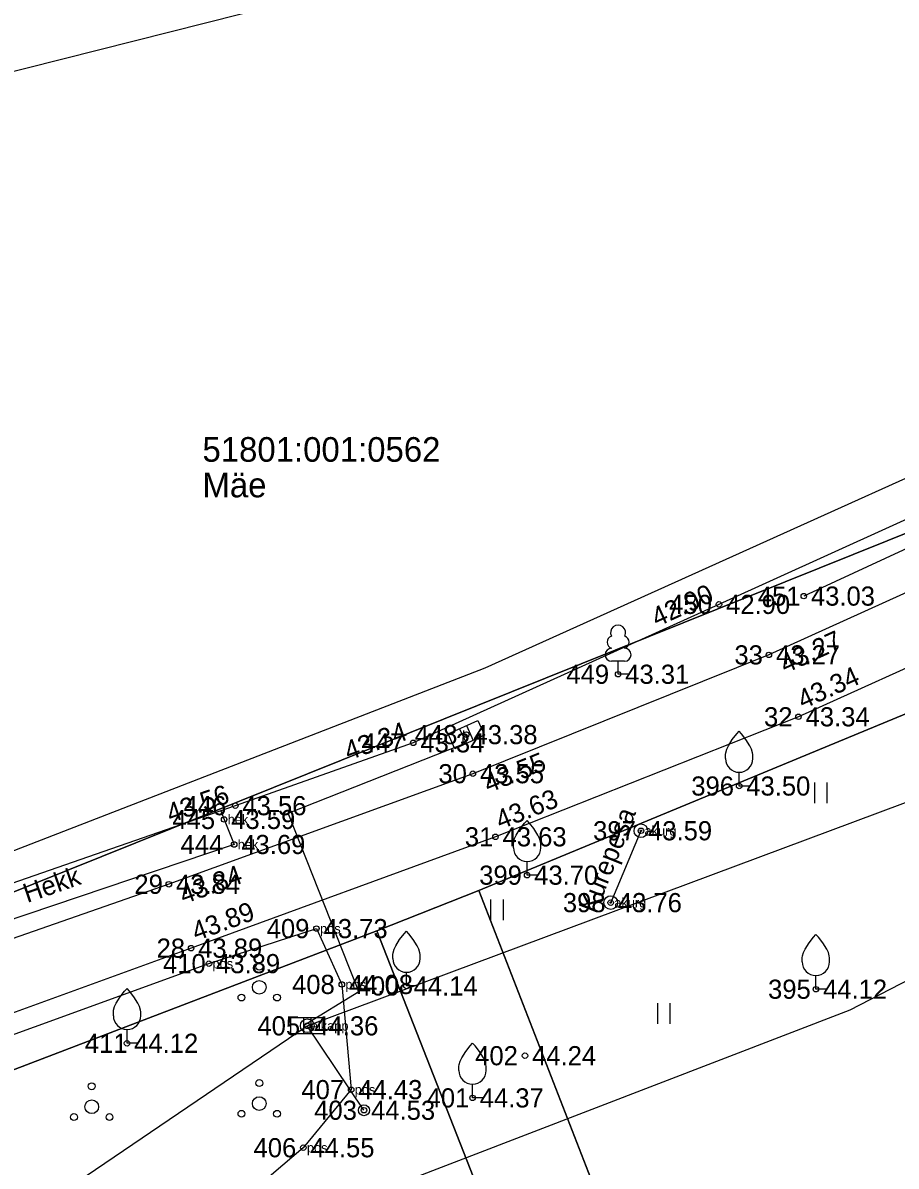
# Model space of a CAD drawing. Extents: x 505800 to 507326, y 6540058 to 6542128.
# Drawn here: x 506036.42 to 506068.35, y 6540204 to 6540245.78 of the extents above; entities that cross this region are included whole.
import ezdxf

# ---------------------------------------------------------------- set-up
doc = ezdxf.new("R2010")
doc.units = 0
for name, color, linetype in [('AED', 7, 'Continuous'), ('ELRAJATISMP', 7, 'Continuous'), ('HALJASTUS', 7, 'Continuous'), ('KORGUS-EH2000', 7, 'Continuous'), ('MAAMUDEL', 7, 'Continuous'), ('MOOTKORG-EH2000', 7, 'Continuous'), ('MOOTMPUNKT', 7, 'Continuous'), ('MOOTNR', 7, 'Continuous'), ('MOOTPIIR', 7, 'Continuous'), ('MPKAABEL', 7, 'Continuous'), ('MPOHULIIN', 7, 'Continuous'), ('PIIR', 7, 'Continuous'), ('POST', 7, 'Continuous'), ('PUU', 7, 'Continuous'), ('RAJATIS', 7, 'Continuous'), ('TEE', 7, 'Continuous')]:
    doc.layers.add(name, color=color, linetype=linetype)

msp = doc.modelspace()

# ---------------------------------------------------------------- linework, layer by layer
at = {"layer": 'AED'}
msp.add_lwpolyline([(506083.03, 6540240.114), (506084.929, 6540234.985), (506074.186, 6540230.116), (506061.873, 6540224.528), (506050.695, 6540219.468), (506044.19, 6540217.171), (506026.923, 6540211.168)], dxfattribs=at)
at = {"layer": 'ELRAJATISMP'}
for p, q in [((506052.392, 6540219.984), (506052.639, 6540219.441)), ((506052.639, 6540220.096), (506052.886, 6540219.553)), ((506046.683, 6540209.425), (506046.683, 6540208.828)), ((506046.955, 6540209.425), (506046.955, 6540208.828))]:
    msp.add_line(p, q, dxfattribs=at)
for points in [[(506051.972, 6540219.793), (506053.059, 6540220.288), (506053.306, 6540219.744), (506052.219, 6540219.249)], [(506046.222, 6540209.425), (506047.416, 6540209.425), (506047.416, 6540208.828), (506046.222, 6540208.828)]]:
    msp.add_lwpolyline(points, close=True, dxfattribs=at)
at = {"layer": 'HALJASTUS'}
for p, q in [((506065.367, 6540218.018), (506065.367, 6540217.257)), ((506065.822, 6540218.018), (506065.822, 6540217.257)), ((506053.526, 6540213.742), (506053.526, 6540212.981)), ((506053.981, 6540213.742), (506053.981, 6540212.981)), ((506059.622, 6540209.956), (506059.622, 6540209.195)), ((506060.077, 6540209.956), (506060.077, 6540209.195))]:
    msp.add_line(p, q, dxfattribs=at)
for points in [[(506088.794, 6540235.545), (506073.899, 6540228.953), (506064.976, 6540224.831)], [(506043.655, 6540216.985), (506043.78, 6540216.669), (506044.148, 6540215.753), (506031.868, 6540211.611), (506031.473, 6540212.75)], [(506046.677, 6540204.671), (506040.966, 6540199.801), (506037.159, 6540200.603), (506032.66, 6540203.527), (506030.725, 6540206.895), (506033.579, 6540207.906), (506043.226, 6540211.399), (506047.158, 6540212.679), (506048.085, 6540210.638), (506048.426, 6540206.794), (506046.677, 6540204.671)]]:
    msp.add_lwpolyline(points, dxfattribs=at)
at = {"layer": 'KORGUS-EH2000'}
for centre in [(506064.976, 6540224.831), (506061.873, 6540224.528), (506063.699, 6540222.682), (506058.186, 6540221.974), (506064.781, 6540220.419), (506052.639, 6540219.769), (506050.695, 6540219.468), (506052.876, 6540218.34), (506062.612, 6540217.89), (506044.19, 6540217.171), (506043.78, 6540216.669), (506053.702, 6540216.033), (506059.021, 6540216.255), (506044.148, 6540215.753), (506054.858, 6540214.632), (506041.76, 6540214.299), (506057.916, 6540213.628), (506047.158, 6540212.679), (506042.573, 6540211.964), (506043.226, 6540211.399), (506048.085, 6540210.638), (506050.449, 6540210.582), (506065.419, 6540210.464), (506046.819, 6540209.126), (506040.231, 6540208.488), (506054.781, 6540208.034), (506048.426, 6540206.794), (506052.866, 6540206.492), (506048.895, 6540206.041), (506046.677, 6540204.671)]:
    msp.add_circle(centre, 0.1, dxfattribs=at)
at = {"layer": 'MOOTMPUNKT'}
for centre in [(506064.976, 6540224.831), (506061.873, 6540224.528), (506063.699, 6540222.682), (506058.186, 6540221.974), (506064.781, 6540220.419), (506052.639, 6540219.769), (506050.695, 6540219.468), (506052.876, 6540218.34), (506062.612, 6540217.89), (506044.19, 6540217.171), (506043.78, 6540216.669), (506053.702, 6540216.033), (506059.021, 6540216.255), (506044.148, 6540215.753), (506054.858, 6540214.632), (506041.76, 6540214.299), (506057.916, 6540213.628), (506047.158, 6540212.679), (506042.573, 6540211.964), (506043.226, 6540211.399), (506048.085, 6540210.638), (506050.449, 6540210.582), (506065.419, 6540210.464), (506046.819, 6540209.126), (506040.231, 6540208.488), (506054.781, 6540208.034), (506048.426, 6540206.794), (506052.866, 6540206.492), (506048.895, 6540206.041), (506046.677, 6540204.671)]:
    msp.add_circle(centre, 0.1, dxfattribs=at)
at = {"layer": 'MOOTPIIR'}
msp.add_lwpolyline([(506098.399, 6540223.506), (506079.917, 6540216.55), (506066.66, 6540209.695), (506043.081, 6540200.619), (506022.167, 6540189.594), (506009.976, 6540186.473), (506006.85, 6540199.643), (506004.777, 6540209.051), (506007.93, 6540210.81), (506012.129, 6540212.088), (506014.395, 6540212.969), (506023.481, 6540210.643), (506053.328, 6540222.211), (506081.494, 6540234.9), (506083.03, 6540240.114), (506097.119, 6540244.795)], dxfattribs=at)
at = {"layer": 'MPKAABEL'}
for points in [[(506046.726, 6540209.167), (506048.708, 6540210.386), (506048.345, 6540211.297), (506047.026, 6540214.617), (506046.12, 6540216.893), (506052.506, 6540219.414), (506052.547, 6540219.917)], [(506048.345, 6540211.297), (506047.026, 6540214.617), (506046.12, 6540216.893)], [(506046.726, 6540209.167), (506048.708, 6540210.386), (506048.345, 6540211.297)]]:
    msp.add_lwpolyline(points, dxfattribs=at)
at = {"layer": 'MPOHULIIN'}
msp.add_lwpolyline([(506023.288, 6540193.167), (506046.819, 6540209.126), (506079.898, 6540221.464), (506112.189, 6540233.927), (506117.49, 6540230.51)], dxfattribs=at)
at = {"layer": 'PIIR'}
for points in [[(505974.82, 6540373.27), (505978.55, 6540356.29), (505982.26, 6540340.2), (505984.17, 6540331.95), (505991.66, 6540295.73), (505997.71, 6540274.55), (506002.06, 6540260.07), (506006.14, 6540246.35), (506007.63, 6540236.84), (506016.86, 6540206.3), (506080.52, 6540231.87), (506081.75, 6540225.93), (506053.1, 6540214.07), (506049.36, 6540212.6), (506018.19, 6540200.68), (506024.58, 6540162.72), (506028.99, 6540136.11), (506032.48, 6540120.26), (506023.4, 6540117.76), (505999.74, 6540236.36), (505986.45, 6540288.25), (505981.09, 6540311.85), (505971.84, 6540354.07), (505949.8, 6540450)], [(506028.99, 6540136.11), (506018.19, 6540200.68), (506049.36, 6540212.6), (506053.99, 6540200.79), (506052.51, 6540200.31), (506055.45, 6540190.69), (506062.61, 6540193.04), (506059.62, 6540202.68), (506057.79, 6540202.01), (506053.1, 6540214.07), (506081.75, 6540225.93), (506090.32, 6540182.64), (506150.17, 6540208.02), (506142.88, 6540238.84), (506158.97, 6540240.95), (506187, 6540243.59), (506198.96, 6540244.45), (506208.53, 6540246.07), (506224.13, 6540249.92), (506272.39, 6540267.75)]]:
    msp.add_lwpolyline(points, dxfattribs=at)
for points in [[(506075.94, 6540254.08), (506080.52, 6540231.87), (506016.86, 6540206.3), (506007.63, 6540236.84)], [(506053.1, 6540214.07), (506057.79, 6540202.01), (506059.62, 6540202.68), (506062.61, 6540193.04), (506055.45, 6540190.69), (506052.51, 6540200.31), (506053.99, 6540200.79), (506049.36, 6540212.6)]]:
    msp.add_lwpolyline(points, close=True, dxfattribs=at)
at = {"layer": 'POST'}
msp.add_lwpolyline([(506048.895, 6540206.041), (506046.819, 6540209.126)], dxfattribs=at)
for centre, radius in [((506059.021, 6540216.255), 0.25), ((506059.021, 6540216.255), 0.0234), ((506057.916, 6540213.628), 0.25), ((506057.916, 6540213.628), 0.0234), ((506046.819, 6540209.126), 0.25), ((506048.895, 6540206.041), 0.2)]:
    msp.add_circle(centre, radius, dxfattribs=at)
at = {"layer": 'PUU'}
for p, q in [((506058.426, 6540222.449), (506057.946, 6540222.449)), ((506058.186, 6540221.974), (506058.186, 6540222.449)), ((506058.566, 6540221.974), (506058.186, 6540221.974)), ((506062.612, 6540217.89), (506062.612, 6540218.39)), ((506063.012, 6540217.89), (506062.612, 6540217.89)), ((506054.858, 6540214.632), (506054.858, 6540215.132)), ((506055.258, 6540214.632), (506054.858, 6540214.632)), ((506050.449, 6540210.582), (506050.449, 6540211.082)), ((506065.419, 6540210.464), (506065.419, 6540210.964)), ((506050.849, 6540210.582), (506050.449, 6540210.582)), ((506065.819, 6540210.464), (506065.419, 6540210.464)), ((506040.231, 6540208.488), (506040.231, 6540208.988)), ((506040.631, 6540208.488), (506040.231, 6540208.488)), ((506052.866, 6540206.492), (506052.866, 6540206.992)), ((506053.266, 6540206.492), (506052.866, 6540206.492))]:
    msp.add_line(p, q, dxfattribs=at)
for points in [[(506062.112, 6540218.89), (506062.112, 6540219.04), (506062.122, 6540219.105), (506062.157, 6540219.235), (506062.217, 6540219.355), (506062.362, 6540219.59), (506062.522, 6540219.795), (506062.612, 6540219.89)], [(506063.112, 6540218.89), (506063.112, 6540219.04), (506063.102, 6540219.105), (506063.067, 6540219.235), (506063.007, 6540219.355), (506062.862, 6540219.59), (506062.702, 6540219.795), (506062.612, 6540219.89)], [(506054.358, 6540215.632), (506054.358, 6540215.782), (506054.368, 6540215.847), (506054.403, 6540215.977), (506054.463, 6540216.097), (506054.608, 6540216.332), (506054.768, 6540216.537), (506054.858, 6540216.632)], [(506055.358, 6540215.632), (506055.358, 6540215.782), (506055.348, 6540215.847), (506055.313, 6540215.977), (506055.253, 6540216.097), (506055.108, 6540216.332), (506054.948, 6540216.537), (506054.858, 6540216.632)], [(506049.949, 6540211.582), (506049.949, 6540211.732), (506049.959, 6540211.797), (506049.994, 6540211.927), (506050.054, 6540212.047), (506050.199, 6540212.282), (506050.359, 6540212.487), (506050.449, 6540212.582)], [(506050.949, 6540211.582), (506050.949, 6540211.732), (506050.939, 6540211.797), (506050.904, 6540211.927), (506050.844, 6540212.047), (506050.699, 6540212.282), (506050.539, 6540212.487), (506050.449, 6540212.582)], [(506064.919, 6540211.464), (506064.919, 6540211.614), (506064.929, 6540211.679), (506064.964, 6540211.809), (506065.024, 6540211.929), (506065.169, 6540212.164), (506065.329, 6540212.369), (506065.419, 6540212.464)], [(506065.919, 6540211.464), (506065.919, 6540211.614), (506065.909, 6540211.679), (506065.874, 6540211.809), (506065.814, 6540211.929), (506065.669, 6540212.164), (506065.509, 6540212.369), (506065.419, 6540212.464)], [(506039.731, 6540209.488), (506039.731, 6540209.638), (506039.741, 6540209.703), (506039.776, 6540209.833), (506039.836, 6540209.953), (506039.981, 6540210.188), (506040.141, 6540210.393), (506040.231, 6540210.488)], [(506040.731, 6540209.488), (506040.731, 6540209.638), (506040.721, 6540209.703), (506040.686, 6540209.833), (506040.626, 6540209.953), (506040.481, 6540210.188), (506040.321, 6540210.393), (506040.231, 6540210.488)], [(506052.366, 6540207.492), (506052.366, 6540207.642), (506052.376, 6540207.707), (506052.411, 6540207.837), (506052.471, 6540207.957), (506052.616, 6540208.192), (506052.776, 6540208.397), (506052.866, 6540208.492)], [(506053.366, 6540207.492), (506053.366, 6540207.642), (506053.356, 6540207.707), (506053.321, 6540207.837), (506053.261, 6540207.957), (506053.116, 6540208.192), (506052.956, 6540208.397), (506052.866, 6540208.492)]]:
    msp.add_lwpolyline(points, dxfattribs=at)
for centre, radius in [((506045.066, 6540211.283), 0.125), ((506045.066, 6540210.533), 0.25), ((506044.416, 6540210.158), 0.125), ((506045.716, 6540210.158), 0.125), ((506038.94, 6540206.916), 0.125), ((506045.066, 6540207.036), 0.125), ((506038.94, 6540206.166), 0.25), ((506045.066, 6540206.286), 0.25), ((506038.29, 6540205.791), 0.125), ((506039.59, 6540205.791), 0.125), ((506044.416, 6540205.911), 0.125), ((506045.716, 6540205.911), 0.125)]:
    msp.add_circle(centre, radius, dxfattribs=at)
for centre, radius, start, end in [((506058.186, 6540223.494), 0.277, 332.5799, 207.4201), ((506058.016, 6540223.147), 0.233, 109.0217, 253.1415), ((506058.356, 6540223.147), 0.233, 286.8508, 70.9859), ((506057.949, 6540222.687), 0.238, 90.0016, 269.3953), ((506058.423, 6540222.687), 0.238, 270.6047, 89.9984), ((506062.612, 6540218.89), 0.5, 180, 0), ((506054.858, 6540215.632), 0.5, 180, 0), ((506050.449, 6540211.582), 0.5, 180, 0), ((506065.419, 6540211.464), 0.5, 180, 0), ((506040.231, 6540209.488), 0.5, 180, 0), ((506052.866, 6540207.492), 0.5, 180, 0)]:
    msp.add_arc(centre, radius, start, end, dxfattribs=at)
at = {"layer": 'RAJATIS'}
msp.add_line((506059.021, 6540216.255), (506057.916, 6540213.628), dxfattribs=at)
at = {"layer": 'TEE'}
for points in [[(506136.149, 6540239.864), (506135.937, 6540240.063), (506132.254, 6540239.999), (506126.638, 6540239.842), (506117.049, 6540238.049), (506105.059, 6540234.886), (506099.56, 6540233.572), (506092.451, 6540231.789), (506085.515, 6540229.625), (506076.748, 6540225.83), (506064.781, 6540220.419), (506053.702, 6540216.033), (506042.573, 6540211.964), (506030.369, 6540207.528), (506023.645, 6540204.818), (506020.115, 6540202.573), (506018.326, 6540200.153), (506016.859, 6540196.696), (506016.712, 6540193.498), (506017.316, 6540188.473)], [(506091.024, 6540234.378), (506084.768, 6540232.16), (506075.613, 6540228.084), (506063.699, 6540222.682), (506052.876, 6540218.34), (506041.76, 6540214.299), (506029.242, 6540209.942), (506022.519, 6540207.387), (506018.387, 6540205.411), (506016.369, 6540204.542), (506014.779, 6540204.825), (506013.879, 6540206.842), (506012.129, 6540212.088)]]:
    msp.add_lwpolyline(points, dxfattribs=at)

# ---------------------------------------------------------------- texts
at = {"layer": 'HALJASTUS'}
msp.add_text('Hekk', height=0.7, rotation=19.0908, dxfattribs=at).set_placement((506036.58, 6540213.612))
at = {"layer": 'KORGUS-EH2000'}
for s, rotation, p in [(' 42.90', 24.3553, (506059.368, 6540223.586)), (' 43.27', 24.3914, (506064.061, 6540221.885)), (' 43.34', 24.3299, (506064.709, 6540220.579)), (' 43.34', 19.447, (506048.082, 6540218.731)), (' 43.55', 21.8597, (506053.202, 6540217.528)), (' 43.56', 19.1714, (506041.576, 6540216.448)), (' 43.63', 21.6001, (506053.638, 6540216.196)), (' 43.84', 19.9776, (506042.059, 6540213.476)), (' 43.89', 20.0812, (506042.513, 6540212.129))]:
    msp.add_text(s, height=0.7, rotation=rotation, dxfattribs=at).set_placement(p)
for s, p in [(' 43.73', (506047.158, 6540212.329)), (' 44.14', (506050.449, 6540210.232)), (' 44.12', (506065.419, 6540210.114)), (' 44.12', (506040.231, 6540208.138)), (' 44.24', (506054.781, 6540207.684)), (' 44.55', (506046.677, 6540204.321))]:
    msp.add_text(s, height=0.7, dxfattribs=at).set_placement(p)
at = {"layer": 'MAAMUDEL'}
for s, p in [(' hek', (506043.78, 6540216.494)), (' akurg', (506059.021, 6540216.08)), (' hek', (506044.148, 6540215.578)), (' akurg', (506057.916, 6540213.453)), (' pos', (506047.158, 6540212.504)), (' pos', (506043.226, 6540211.224)), (' pos', (506048.085, 6540210.463)), (' elkapp', (506046.819, 6540208.951)), (' pos', (506048.426, 6540206.619)), (' pos', (506046.677, 6540204.496))]:
    msp.add_text(s, height=0.35, dxfattribs=at).set_placement(p)
at = {"layer": 'MOOTKORG-EH2000'}
for s, p in [(' 43.03', (506064.976, 6540224.481)), (' 42.90', (506061.873, 6540224.178)), (' 43.27', (506063.699, 6540222.332)), (' 43.31', (506058.186, 6540221.624)), (' 43.34', (506064.781, 6540220.069)), (' 43.38', (506052.639, 6540219.419)), (' 43.34', (506050.695, 6540219.118)), (' 43.55', (506052.876, 6540217.99)), (' 43.50', (506062.612, 6540217.54)), (' 43.56', (506044.19, 6540216.821)), (' 43.59', (506043.78, 6540216.319)), (' 43.63', (506053.702, 6540215.683)), (' 43.59', (506059.021, 6540215.905)), (' 43.69', (506044.148, 6540215.403)), (' 43.70', (506054.858, 6540214.282)), (' 43.84', (506041.76, 6540213.949)), (' 43.76', (506057.916, 6540213.278)), (' 43.73', (506047.158, 6540212.329)), (' 43.89', (506042.573, 6540211.614)), (' 43.89', (506043.226, 6540211.049)), (' 44.08', (506048.085, 6540210.288)), (' 44.14', (506050.449, 6540210.232)), (' 44.12', (506065.419, 6540210.114)), (' 44.36', (506046.819, 6540208.776)), (' 44.12', (506040.231, 6540208.138)), (' 44.24', (506054.781, 6540207.684)), (' 44.43', (506048.426, 6540206.444)), (' 44.37', (506052.866, 6540206.142)), (' 44.53', (506048.895, 6540205.691)), (' 44.55', (506046.677, 6540204.321))]:
    msp.add_text(s, height=0.7, dxfattribs=at).set_placement(p)
at = {"layer": 'MOOTNR'}
for s, p in [('451 ', (506063.296, 6540224.481)), ('450 ', (506060.053, 6540224.178)), ('33 ', (506062.439, 6540222.332)), ('449 ', (506056.296, 6540221.624)), ('32 ', (506063.521, 6540220.069)), ('448 ', (506050.749, 6540219.419)), ('447 ', (506048.805, 6540219.118)), ('30 ', (506051.616, 6540217.99)), ('396 ', (506060.862, 6540217.54)), ('446 ', (506042.3, 6540216.821)), ('445 ', (506041.89, 6540216.319)), ('31 ', (506052.582, 6540215.683)), ('397 ', (506057.271, 6540215.905)), ('444 ', (506042.189, 6540215.403)), ('399 ', (506053.108, 6540214.282)), ('29 ', (506040.5, 6540213.949)), ('398 ', (506056.166, 6540213.278)), ('409 ', (506045.338, 6540212.329)), ('28 ', (506041.313, 6540211.614)), ('410 ', (506041.546, 6540211.049)), ('408 ', (506046.265, 6540210.288)), ('400 ', (506048.629, 6540210.232)), ('395 ', (506063.669, 6540210.114)), ('405 ', (506044.999, 6540208.776)), ('411 ', (506038.691, 6540208.138)), ('402 ', (506052.961, 6540207.684)), ('407 ', (506046.606, 6540206.444)), ('401 ', (506051.186, 6540206.142)), ('403 ', (506047.075, 6540205.691)), ('406 ', (506044.858, 6540204.321))]:
    msp.add_text(s, height=0.7, dxfattribs=at).set_placement(p)
at = {"layer": 'PIIR'}
for s, p in [('51801:001:0562', (506042.989, 6540229.74)), ('Mäe', (506042.989, 6540228.44))]:
    msp.add_text(s, height=0.9, dxfattribs=at).set_placement(p)
at = {"layer": 'RAJATIS'}
msp.add_text('Kurepesa', height=0.7, rotation=68.3154, dxfattribs=at).set_placement((506057.371, 6540213.198))

doc.saveas('drawing.dxf')
